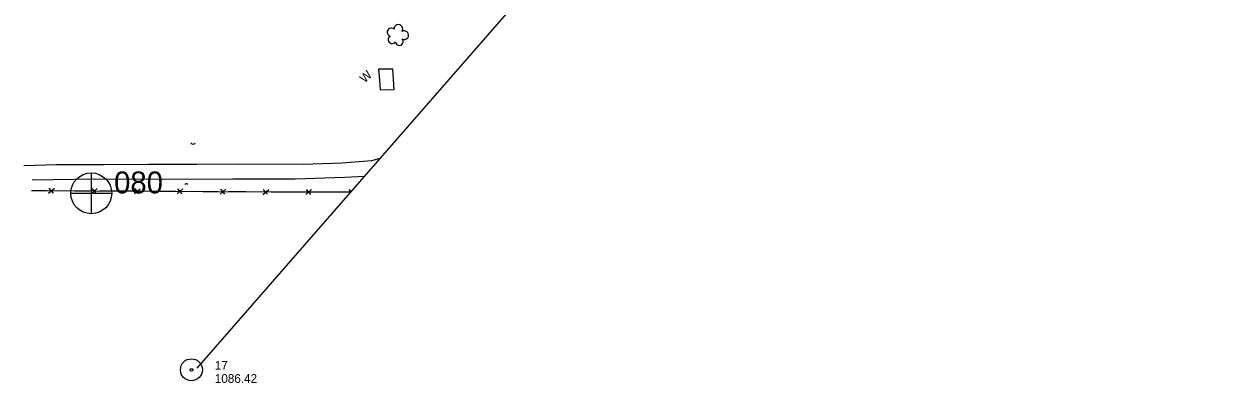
# Model space of a CAD drawing. Extents: x 296021 to 298261, y 27813 to 30404.
# Drawn here: x 296748 to 297569, y 28594 to 28840 of the extents above; entities that cross this region are included whole.
import ezdxf

# ---------------------------------------------------------------- set-up
doc = ezdxf.new("R2010")
doc.units = 0
for name, color, linetype in [('Level 15', 7, 'Continuous'), ('Level 17', 7, 'Continuous'), ('Level 18', 7, 'Continuous'), ('Level 4', 7, 'Continuous'), ('Level 6', 7, 'Continuous')]:
    doc.layers.add(name, color=color, linetype=linetype)

msp = doc.modelspace()

# ---------------------------------------------------------------- linework, layer by layer
at = {"layer": 'Level 15'}
for p, q in [((296765.23, 28723.86), (296769.16, 28727.26)), ((296765.42, 28727.27), (296768.35, 28723.92)), ((296794.57, 28723.73), (296798.5, 28727.12)), ((296794.77, 28727.14), (296797.7, 28723.79)), ((296823.92, 28723.6), (296827.85, 28726.99)), ((296824.11, 28727.01), (296827.04, 28723.65)), ((296853.26, 28723.44), (296857.2, 28726.83)), ((296853.46, 28726.85), (296856.39, 28723.5)), ((296882.61, 28723.27), (296886.54, 28726.65)), ((296882.81, 28726.68), (296885.73, 28723.32)), ((296911.95, 28723.09), (296915.89, 28726.48)), ((296912.15, 28726.5), (296915.08, 28723.14)), ((296941.3, 28722.99), (296945.23, 28726.4)), ((296941.49, 28726.4), (296944.43, 28723.06)), ((296970.84, 28726.33), (296972.11, 28724.88))]:
    msp.add_line(p, q, dxfattribs=at)
for points in [[(297001.88, 28794.98), (297000.83, 28808.91), (296991.1, 28808.77)], [(296991.1, 28808.77), (296991.72, 28801.28), (296992.15, 28794.66), (297001.88, 28794.98)], [(296753.53, 28725.75), (296764.01, 28725.7)], [(296753.53, 28725.75), (296841.35, 28725.35), (296917.55, 28724.89), (296971.99, 28724.75)], [(296770.95, 28725.67), (296782.87, 28725.61)], [(296782.87, 28725.61), (296793.36, 28725.57)], [(296800.29, 28725.53), (296812.22, 28725.48)], [(296812.22, 28725.48), (296822.71, 28725.43)], [(296829.64, 28725.4), (296841.35, 28725.35), (296841.56, 28725.35)], [(296841.56, 28725.35), (296852.05, 28725.28)], [(296858.98, 28725.24), (296870.91, 28725.17)], [(296870.91, 28725.17), (296881.4, 28725.1)], [(296888.33, 28725.06), (296900.25, 28724.99)], [(296900.25, 28724.99), (296910.74, 28724.93)], [(296917.67, 28724.89), (296929.6, 28724.85)], [(296929.6, 28724.85), (296940.09, 28724.83)], [(296947.02, 28724.81), (296958.95, 28724.78)], [(296958.95, 28724.78), (296969.43, 28724.75)]]:
    msp.add_lwpolyline(points, dxfattribs=at)
for centre, radius, start, end in [((296864.13, 28759.45), 1.9, 214.72547, 320.96503), ((296859.51, 28729.02), 1.3, 44.47407, 150.71363)]:
    msp.add_arc(centre, radius, start, end, dxfattribs=at)
at = {"layer": 'Level 17'}
for points in [[(296748.35, 28742.76), (296770.59, 28743.53), (296803.36, 28743.57), (296833.63, 28743.75), (296866.71, 28743.79), (296895.45, 28743.93), (296939.5, 28743.75), (296966.22, 28744.73), (296986.5, 28746.39), (296992.12, 28747.81)], [(296753.87, 28733), (296796.69, 28733.62), (296842.95, 28733.47), (296891.34, 28733.62), (296934.05, 28733.73), (296968.05, 28734.78), (296981.5, 28735.64)]]:
    msp.add_lwpolyline(points, dxfattribs=at)
at = {"layer": 'Level 18'}
for centre, radius, start, end in [((296999.83, 28834.16), 2.78, 45.63746, 253.41046), ((297004.74, 28836.34), 2.97, 322.66657, 183.90046), ((297008.74, 28832.07), 2.97, 240.31739, 123.29066), ((297000.52, 28829.14), 2.78, 122.31448, 323.32553), ((297005.36, 28827.71), 2.61, 185.02263, 42.95523)]:
    msp.add_arc(centre, radius, start, end, dxfattribs=at)
at = {"layer": 'Level 4'}
for p, q in [((296794.33, 28737.85), (296794.27, 28710)), ((296780.42, 28723.82), (296808.33, 28723.81))]:
    msp.add_line(p, q, dxfattribs=at)
msp.add_lwpolyline([(297569.31, 29463.18), (297175.77, 28958.23), (296866.66, 28604.06)], dxfattribs=at)
msp.add_circle((296794.39, 28723.83), 14, dxfattribs=at)
at = {"layer": 'Level 6'}
for radius in [7.5, 0.96]:
    msp.add_circle((296862.98, 28603.02), radius, dxfattribs=at)

# ---------------------------------------------------------------- texts
at = {"layer": 'Level 15'}
msp.add_text('W', height=6, rotation=44.24292, dxfattribs=at).set_placement((296981.73, 28798.99))
at = {"layer": 'Level 4'}
msp.add_text('080', height=15, dxfattribs=at).set_placement((296810.04, 28723.76))
at = {"layer": 'Level 6'}
for s, p in [('17', (296878.98, 28603.02)), ('1086.42', (296878.98, 28594.02))]:
    msp.add_text(s, height=6, dxfattribs=at).set_placement(p)

doc.saveas('drawing.dxf')
